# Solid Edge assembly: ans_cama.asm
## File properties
Author: ion
Template: Iso Assembly.asm
Last saved by: user
Revision: 6
Application: Solid Edge
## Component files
arbore.par
cama.par
suport.par
rola.par
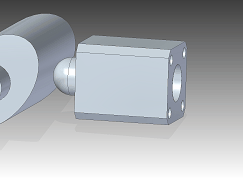
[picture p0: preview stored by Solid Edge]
